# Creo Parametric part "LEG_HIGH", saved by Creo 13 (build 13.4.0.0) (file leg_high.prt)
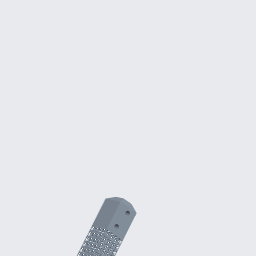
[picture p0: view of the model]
Units: millimeter Newton Second (mmNs); MM, TONNE, SECS
Materials in the file: PLA

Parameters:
  PTC_MATERIAL_NAME = "PLA"
  GRANTA_DATALINK_VERSION = "5"
  GRANTA_DATABASE_KEY = "Granta_Typical_Materials"
  GRANTA_IDENTITY_GUID = "b9b893b2-6906-4609-ab08-d879fcb43028"
  GRANTA_VERSION_GUID = "46d219ad-0776-45d4-90e4-94de701ee33b"
  GRANTA_MODEL_REFERENCE = "00000000-0000-0000-0000-000000000000"

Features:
  1. datum plane "RIGHT"
  2. datum plane "TOP"
  3. datum plane "FRONT"
  4. coordinate system
  5. protrusion
  6. protrusion
  7. protrusion

Other named items: LATTICE_1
